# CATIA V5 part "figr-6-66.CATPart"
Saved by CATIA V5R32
Part number: Part2
Bounding box of the stored display mesh (mm): x -31.464 to 31.464, y -26.321 to 36.69, z 59.463 to 122.391
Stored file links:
  D:\PROJECTS\Project 2022\CATIA V5 6R 2022\Resources\Part Files\c06_catia_v5_6r2022_prt\figr-6-66.CATPart
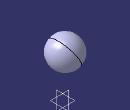
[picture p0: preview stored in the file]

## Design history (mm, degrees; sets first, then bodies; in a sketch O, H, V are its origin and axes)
Body1 (main body)
  Sketch1 on yz-plane, origin (0, 0, 0), H (0, 1, 0), V (0, 0, 1)
    axis line L1 (-55.8323, 90.9269) -> (61.0167, 90.9269)
    arc A1 centre (5.1844, 90.9269) radius 31.5054 from (36.6898, 90.9269) to (-26.3209, 90.9269) ccw
    point P3 (5.1844, 90.9269)
    point P4 (36.6898, 90.9269)
    point P5 (-26.3209, 90.9269)
    line L2 (-26.3209, 90.9269) -> (36.6898, 90.9269)
    horizontal: L1 H, L2 H
    coincidence: P3 L1, P4 L1, P5 L1
  Shaft1: profile Sketch1, axis Sketch1.L1, angle 360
